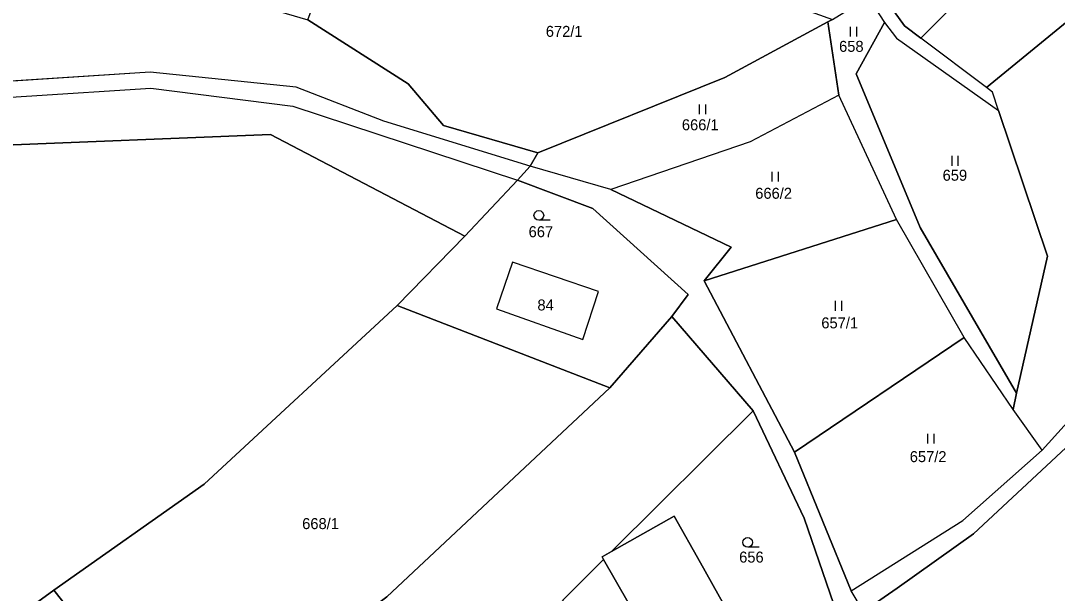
# Model space of a CAD drawing. Extents: x -590606 to -587796, y -1065936 to -1062515.
# Drawn here: x -589718.9 to -589558.4, y -1064760.8 to -1064672.2 of the extents above; entities that cross this region are included whole.
import ezdxf

# ---------------------------------------------------------------- set-up
doc = ezdxf.new("R2010")
doc.units = 0
for name, color, linetype in [('Parcela nároku', 7, 'Continuous'), ('Vnější obvod_ Studené', 7, 'Continuous'), ('Vrstva 30', 7, 'Continuous'), ('Územní plán', 7, 'Continuous')]:
    doc.layers.add(name, color=color, linetype=linetype)

msp = doc.modelspace()

# ---------------------------------------------------------------- linework, layer by layer
at = {"layer": 'Parcela nároku'}
for points in [[(-589753.3, -1064666.31), (-589751.87, -1064684.47), (-589758.89, -1064685.17), (-589755.37, -1064668.5), (-589765.53, -1064670.88), (-589769.01, -1064656.08), (-589753.92, -1064654.08), (-589730.86, -1064655.58), (-589674.51, -1064672.1), (-589658.93, -1064681.99), (-589653.5, -1064688.41), (-589638.89, -1064692.66), (-589640.04, -1064694.73), (-589662.7, -1064687.77), (-589676.27, -1064682.49), (-589698.92, -1064680.19), (-589732.55, -1064682.34), (-589733.53, -1064672.91), (-589741.81, -1064673.48), (-589742.61, -1064665.31)], [(-589667.65, -1064653.64), (-589635.57, -1064656.82), (-589593.25, -1064672.02), (-589593.95, -1064672.4), (-589609.9, -1064681.01), (-589638.89, -1064692.66), (-589653.5, -1064688.41), (-589658.93, -1064681.99), (-589674.51, -1064672.1)], [(-589579.59, -1064674.92), (-589567.91, -1064663.13), (-589562.54, -1064658.03), (-589561.08, -1064660), (-589553.65, -1064654.07), (-589548.24, -1064668.99), (-589556.93, -1064672.33), (-589569.41, -1064682.53)], [(-589567.91, -1064663.13), (-589575.32, -1064655.99), (-589586.37, -1064667), (-589582.11, -1064672.99), (-589579.59, -1064674.92)], [(-589569.41, -1064682.53), (-589579.59, -1064674.92), (-589582.11, -1064672.99), (-589586.37, -1064667), (-589587.72, -1064668.56), (-589585.22, -1064672.49), (-589583.34, -1064674.92), (-589567.53, -1064686.1), (-589568.49, -1064683.25)], [(-589593.25, -1064672.02), (-589587.72, -1064668.56), (-589585.22, -1064672.49), (-589589.6, -1064680.44), (-589579.69, -1064704.22), (-589564.75, -1064729.88), (-589565.29, -1064732.38), (-589572.86, -1064721.23), (-589583.32, -1064702.97), (-589592.26, -1064683.72), (-589593.95, -1064672.4)], [(-589609.9, -1064681.01), (-589593.95, -1064672.4), (-589592.26, -1064683.72), (-589605.99, -1064690.98), (-589627.55, -1064698.31), (-589640.04, -1064694.73), (-589638.89, -1064692.66)], [(-589583.34, -1064674.92), (-589567.53, -1064686.1), (-589559.97, -1064708.63), (-589564.75, -1064729.88), (-589579.69, -1064704.22), (-589589.6, -1064680.44), (-589585.22, -1064672.49)], [(-589539.89, -1064691.66), (-589534.4, -1064689.91), (-589529.23, -1064688.37), (-589522.89, -1064698.36), (-589530.19, -1064704.81), (-589560.8, -1064738.7), (-589565.29, -1064732.38), (-589564.75, -1064729.88), (-589559.97, -1064708.63), (-589567.53, -1064686.1), (-589568.49, -1064683.25), (-589569.41, -1064682.53), (-589556.93, -1064672.33), (-589554.98, -1064677.87), (-589548.15, -1064696.48), (-589539.26, -1064693.64)], [(-589522.89, -1064698.36), (-589513.75, -1064690.35), (-589497.56, -1064678.5), (-589496.63, -1064681.82), (-589511.03, -1064691.51), (-589528.63, -1064706.39), (-589554.07, -1064735.46), (-589571.42, -1064751.62), (-589583.26, -1064760.02), (-589588.45, -1064763.67), (-589590.38, -1064760.46), (-589573.06, -1064749.58), (-589560.8, -1064738.7), (-589530.19, -1064704.81)], [(-589740.69, -1064692.4), (-589736.77, -1064692.13), (-589737.33, -1064685.11), (-589698.77, -1064682.65), (-589676.81, -1064685.44), (-589642, -1064696.9), (-589650.2, -1064705.57), (-589680.26, -1064689.83), (-589724.05, -1064691.59), (-589723.58, -1064702.36), (-589778.73, -1064718.01), (-589777.67, -1064709.79), (-589759.62, -1064700.86), (-589757.03, -1064687.42), (-589741.31, -1064685.44)], [(-589583.32, -1064702.97), (-589592.26, -1064683.72), (-589605.99, -1064690.98), (-589627.55, -1064698.31), (-589608.96, -1064707.26), (-589613.14, -1064712.47)], [(-589680.26, -1064689.83), (-589650.2, -1064705.57), (-589660.64, -1064716.31), (-589690.55, -1064743.96), (-589713.8, -1064760.35), (-589721.04, -1064765.62), (-589866.87, -1064751.2), (-589844.17, -1064740.14), (-589796.41, -1064719.77), (-589777.67, -1064709.79), (-589778.73, -1064718.01), (-589723.58, -1064702.36), (-589724.05, -1064691.59)], [(-589615.6, -1064714.57), (-589630.34, -1064701.27), (-589642, -1064696.9), (-589650.2, -1064705.57), (-589660.64, -1064716.31), (-589627.72, -1064729.04), (-589618.13, -1064717.98)], [(-589572.86, -1064721.23), (-589583.32, -1064702.97), (-589613.14, -1064712.47), (-589599.12, -1064738.99)], [(-589629.5, -1064714.1), (-589642.79, -1064709.59), (-589645.25, -1064716.83), (-589631.89, -1064721.53)], [(-589631.89, -1064721.53), (-589629.5, -1064714.1), (-589642.79, -1064709.59), (-589645.25, -1064716.83)], [(-589627.72, -1064729.04), (-589660.64, -1064716.31), (-589690.55, -1064743.96), (-589713.8, -1064760.35), (-589694.16, -1064785.11), (-589662.24, -1064761.36)], [(-589605.54, -1064732.57), (-589618.13, -1064717.98), (-589627.72, -1064729.04), (-589662.24, -1064761.36), (-589694.16, -1064785.11), (-589664.99, -1064821.89), (-589630.44, -1064800.11), (-589618.14, -1064787.77), (-589635.08, -1064761.95), (-589628.69, -1064755.59), (-589628.92, -1064755.19), (-589627.45, -1064754.35)], [(-589560.8, -1064738.7), (-589565.29, -1064732.38), (-589572.86, -1064721.23), (-589599.12, -1064738.99), (-589590.38, -1064760.46), (-589573.06, -1064749.58)], [(-589593.02, -1064762.59), (-589597.63, -1064749.22), (-589605.54, -1064732.57), (-589627.45, -1064754.35), (-589617.78, -1064748.87), (-589613.71, -1064756.12), (-589605.65, -1064770.49), (-589616.76, -1064776.62), (-589624.91, -1064762.26), (-589628.69, -1064755.59), (-589635.08, -1064761.95), (-589618.14, -1064787.77)], [(-589583.26, -1064760.02), (-589571.42, -1064751.62), (-589554.07, -1064735.46), (-589553.84, -1064737.2), (-589552.16, -1064749.21), (-589536.47, -1064792.4), (-589565.9, -1064825.54), (-589588.45, -1064763.67)], [(-589605.65, -1064770.49), (-589613.71, -1064756.12), (-589617.78, -1064748.87), (-589627.45, -1064754.35), (-589628.92, -1064755.19), (-589628.69, -1064755.59), (-589624.91, -1064762.26), (-589616.76, -1064776.62)], [(-589848.05, -1064822.46), (-589781.14, -1064797.6), (-589732.48, -1064773.33), (-589721.04, -1064765.62), (-589713.8, -1064760.35), (-589694.16, -1064785.11), (-589709.51, -1064796.54), (-589749.8, -1064818.94), (-589790.83, -1064834.34), (-589885.81, -1064873.92), (-589959.21, -1064893.84), (-589981.68, -1064896.99), (-590005.25, -1064904.42), (-590008.77, -1064887.64), (-590008.01, -1064872.65), (-589965.99, -1064862.62)]]:
    msp.add_lwpolyline(points, close=True, dxfattribs=at)
for points in [[(-589588.45, -1064763.67), (-589590.38, -1064760.46), (-589599.12, -1064738.99), (-589613.14, -1064712.47), (-589608.96, -1064707.26), (-589627.55, -1064698.31), (-589640.04, -1064694.73), (-589662.7, -1064687.77), (-589676.27, -1064682.49), (-589698.92, -1064680.19), (-589732.55, -1064682.34), (-589751.87, -1064684.47), (-589758.89, -1064685.17), (-589783.78, -1064691.12), (-589800.98, -1064692.6), (-589815.56, -1064693.85)], [(-589817.72, -1064696.23), (-589783.04, -1064692.55), (-589759.39, -1064687.91), (-589757.03, -1064687.42), (-589741.31, -1064685.44), (-589737.33, -1064685.11), (-589698.77, -1064682.65), (-589676.81, -1064685.44), (-589642, -1064696.9), (-589630.34, -1064701.27), (-589615.6, -1064714.57), (-589618.13, -1064717.98), (-589605.54, -1064732.57), (-589597.63, -1064749.22), (-589593.02, -1064762.59)]]:
    msp.add_lwpolyline(points, dxfattribs=at)
at = {"layer": 'Vnější obvod_ Studené'}
for p, q in [((-589698.92, -1064680.19), (-589732.55, -1064682.34)), ((-589676.27, -1064682.49), (-589698.92, -1064680.19)), ((-589662.7, -1064687.77), (-589676.27, -1064682.49)), ((-589640.04, -1064694.73), (-589662.7, -1064687.77)), ((-589642, -1064696.9), (-589640.04, -1064694.73)), ((-589650.2, -1064705.57), (-589642, -1064696.9)), ((-589660.64, -1064716.31), (-589650.2, -1064705.57)), ((-589627.72, -1064729.04), (-589660.64, -1064716.31)), ((-589618.13, -1064717.98), (-589627.72, -1064729.04)), ((-589605.54, -1064732.57), (-589618.13, -1064717.98)), ((-589627.45, -1064754.35), (-589605.54, -1064732.57)), ((-589628.92, -1064755.19), (-589627.45, -1064754.35)), ((-589628.69, -1064755.59), (-589628.92, -1064755.19)), ((-589635.08, -1064761.95), (-589628.69, -1064755.59))]:
    msp.add_line(p, q, dxfattribs=at)
at = {"layer": 'Vrstva 30'}
for p, q in [((-589590.52, -1064673.15), (-589590.52, -1064674.65)), ((-589589.49, -1064674.65), (-589589.49, -1064673.15)), ((-589613.89, -1064685.18), (-589613.89, -1064686.68)), ((-589612.86, -1064686.68), (-589612.86, -1064685.18)), ((-589574.79, -1064693.15), (-589574.79, -1064694.65)), ((-589573.77, -1064694.65), (-589573.77, -1064693.15)), ((-589602.65, -1064695.6), (-589602.65, -1064697.1)), ((-589601.62, -1064697.1), (-589601.62, -1064695.6)), ((-589636.97, -1064703.1), (-589638.72, -1064703.1)), ((-589592.84, -1064715.59), (-589592.84, -1064717.09)), ((-589591.82, -1064717.09), (-589591.82, -1064715.59)), ((-589578.54, -1064736.17), (-589578.54, -1064737.67)), ((-589577.52, -1064737.67), (-589577.52, -1064736.17)), ((-589604.63, -1064753.71), (-589606.38, -1064753.71))]:
    msp.add_line(p, q, dxfattribs=at)
for centre in [(-589638.72, -1064702.35), (-589606.38, -1064752.96)]:
    msp.add_circle(centre, 0.75, dxfattribs=at)
at = {"layer": 'Územní plán'}
msp.add_lwpolyline([(-589664.99, -1064821.89), (-589694.16, -1064785.11), (-589713.8, -1064760.35), (-589690.55, -1064743.96), (-589660.64, -1064716.31)], dxfattribs=at)

# ---------------------------------------------------------------- texts
at = {"layer": 'Parcela nároku'}
for s, p in [('672/1', (-589637.64, -1064674.71)), ('658', (-589592.23, -1064677.03)), ('666/1', (-589616.57, -1064689.17)), ('659', (-589576.2, -1064696.98)), ('666/2', (-589605.21, -1064699.77)), ('667', (-589640.3, -1064705.72)), ('84', (-589638.94, -1064717.06)), ('657/1', (-589594.98, -1064719.83)), ('657/2', (-589581.29, -1064740.53)), ('668/1', (-589675.36, -1064750.9)), ('656', (-589607.7, -1064756.08))]:
    msp.add_text(s, height=1.7, dxfattribs=at).set_placement(p)

doc.saveas('drawing.dxf')
